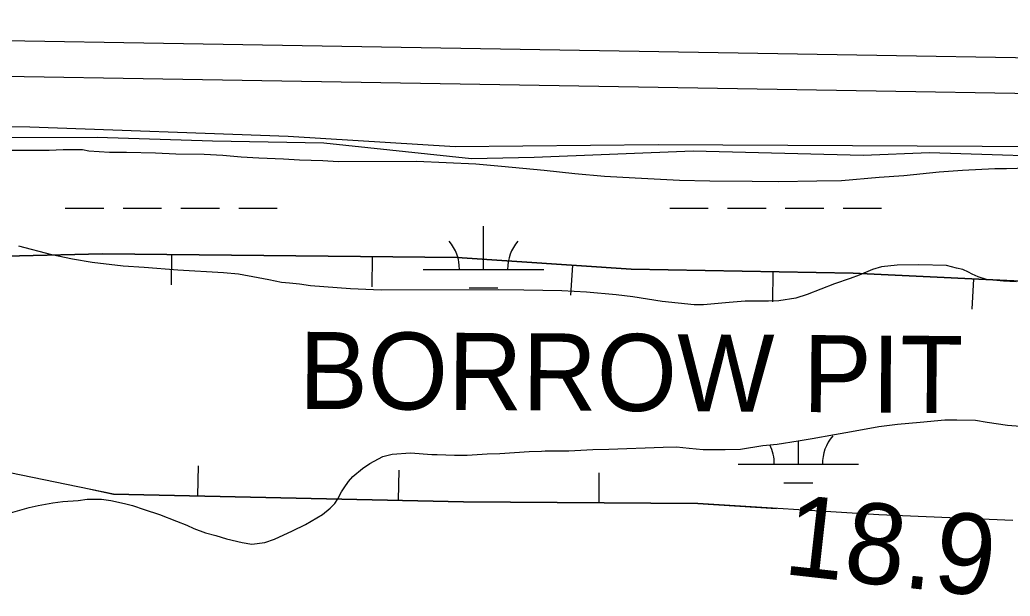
# Model space of a CAD drawing. Extents: x 3445503 to 3483459, y 540493 to 566012.
# Drawn here: x 3465896 to 3466718, y 552977 to 553456 of the extents above; entities that cross this region are included whole.
import ezdxf

# ---------------------------------------------------------------- set-up
doc = ezdxf.new("R2010")
doc.units = 0
for name, color, linetype in [('V-BORW-IDEN', 7, 'Continuous'), ('V-BORW-LINE', 7, 'Continuous'), ('V-LEVE-TOET', 7, 'Continuous'), ('V-RIVR-RANG', 7, 'Continuous'), ('V-SITE-VEGE', 7, 'Continuous'), ('V-SURV-LINE', 7, 'Continuous'), ('V-WETL-SWMP', 7, 'Continuous')]:
    doc.layers.add(name, color=color, linetype=linetype)

msp = doc.modelspace()

# ---------------------------------------------------------------- linework, layer by layer
at = {"layer": 'V-BORW-LINE'}
for p, q in [((3466021.74, 553261.05), (3466021.49, 553236.05)), ((3466188.33, 553259.35), (3466188.08, 553234.35)), ((3466354.72, 553252.24), (3466353.05, 553227.3)), ((3466521.19, 553246.8), (3466520.73, 553221.81)), ((3466687.67, 553240.87), (3466686.49, 553215.9)), ((3466043.69, 553060.73), (3466044.24, 553085.72)), ((3466210.25, 553057.07), (3466210.8, 553082.07)), ((3466376.83, 553054.95), (3466377.04, 553079.94))]:
    msp.add_line(p, q, dxfattribs=at)
for points in [[(3464755.94, 553241.74), (3464860.3, 553253.78), (3464945.02, 553233.84), (3464976, 553179.35), (3465019.34, 553224.51), (3465044.07, 553250.35), (3465137.34, 553252.47), (3465300.09, 553251.41), (3465457.21, 553261.25), (3465601.57, 553261.39), (3465688.95, 553257.71), (3465814.69, 553258.09), (3465964.49, 553261.63), (3466258.98, 553258.64), (3466403.46, 553248.99), (3466587.71, 553245.57), (3466756.03, 553237.65)], [(3466756.03, 553237.65), (3466587.71, 553245.57), (3466403.46, 553248.99), (3466258.98, 553258.64), (3465964.49, 553261.63), (3465814.69, 553258.09), (3465688.95, 553257.71), (3465601.57, 553261.39), (3465457.21, 553261.25), (3465300.09, 553251.41), (3465137.34, 553252.47), (3465044.07, 553250.35), (3465019.34, 553224.51), (3464976, 553179.35), (3464945.02, 553233.84), (3464860.3, 553253.78), (3464755.94, 553241.74)], [(3466720.32, 553040.35), (3466609.07, 553044.93), (3466458.87, 553054.26), (3466264.38, 553055.88), (3465973.67, 553062.27), (3465790.42, 553099.82), (3465601.82, 553107.72), (3465427.44, 553085.02), (3465258.2, 553090.06), (3465125.53, 553090.31), (3464961.14, 553070.6), (3464793.44, 553028.89)], [(3465954.38, 553066.22), (3465973.67, 553062.27), (3466264.38, 553055.88), (3466458.87, 553054.26), (3466524.1, 553050.21)]]:
    msp.add_lwpolyline(points, dxfattribs=at)
at = {"layer": 'V-LEVE-TOET'}
msp.add_lwpolyline([(3465299.58, 553374.06), (3465570.24, 553371.6), (3465904.01, 553367.37), (3466118.73, 553359.54), (3466257.34, 553350.84), (3466425.84, 553352.63), (3466748.55, 553350.98), (3467041.34, 553344.68), (3467298.34, 553340.88)], dxfattribs=at)
at = {"layer": 'V-SITE-VEGE'}
for points in [[(3465881.66, 553347.86), (3465920.18, 553347.98), (3465931.86, 553348.33), (3465947.96, 553348.37), (3465953.02, 553347.44), (3465970.38, 553346.23), (3465984.27, 553346.27), (3466008.59, 553345.71), (3466025.32, 553344.81), (3466049, 553344.56), (3466064.48, 553343.66), (3466079.64, 553342.45), (3466094.16, 553341.54), (3466114.68, 553340.65), (3466127.95, 553339.74), (3466147.53, 553339.17), (3466160.16, 553338.58), (3466225.2, 553338.77), (3466274.46, 553336.39), (3466295.93, 553334.56), (3466331.3, 553331.18), (3466356.57, 553328.42), (3466381.2, 553326.28), (3466406.78, 553324.77), (3466443.72, 553322.99), (3466468.67, 553322.43), (3466504.03, 553322.22), (3466525.82, 553321.97), (3466557.71, 553322.38), (3466578.23, 553322.75), (3466609.48, 553325.37), (3466629.99, 553326.69), (3466659.35, 553329.94), (3466678.6, 553331.25), (3466705.44, 553332.6), (3466715.22, 553332.62), (3466742.06, 553333.33)], [(3466723.2, 553238.55), (3466712.78, 553239.15), (3466698.56, 553240.37), (3466691.61, 553242.56), (3466686.55, 553244.76), (3466683.71, 553246.64), (3466678.96, 553248.84), (3466673.6, 553249.77), (3466665.38, 553251.96), (3466642.33, 553252.52), (3466624.33, 553252.47), (3466611.39, 553250.85), (3466603.82, 553248.62), (3466592.79, 553244.17), (3466585.22, 553241.3), (3466572.29, 553236.84), (3466549.58, 553227.94), (3466540.12, 553225.07), (3466526.23, 553222.82), (3466517.39, 553222.48), (3466498.13, 553222.42), (3466484.87, 553221.43), (3466463.41, 553219.48), (3466455.83, 553219.45), (3466429.3, 553222.22), (3466404.98, 553225.94), (3466391.08, 553227.79), (3466366.45, 553229.93), (3466345.93, 553231.13), (3466314.35, 553231.67), (3466293.2, 553231.92), (3466195.95, 553231.64), (3466170.38, 553232.82), (3466137.22, 553235.25), (3466128.06, 553236.49), (3466119.84, 553237.41), (3466113.21, 553238.02), (3466102.47, 553240.2), (3466093.63, 553241.76), (3466077.52, 553244.87), (3466064.89, 553246.09), (3466026.99, 553248.19), (3465999.2, 553250.32), (3465981.52, 553251.53), (3465955.93, 553254.61), (3465939.51, 553257.41), (3465922.45, 553260.83), (3465894.96, 553268.01)], [(3466122.34, 553031.57), (3466133.06, 553036.96), (3466147.25, 553045.21), (3466153.54, 553050.6), (3466157.32, 553054.4), (3466159.84, 553058.2), (3466162.98, 553064.2), (3466165.18, 553067.37), (3466168.64, 553072.74), (3466172.41, 553076.86), (3466180.29, 553083.52), (3466186.59, 553087.64), (3466197.31, 553093.35), (3466204.88, 553095.27), (3466220.35, 553096.58), (3466238.03, 553095.05), (3466242.45, 553095.06), (3466256.66, 553094.47), (3466267.39, 553094.51), (3466283.81, 553095.5), (3466294.54, 553095.85), (3466318.85, 553097.5), (3466328.95, 553097.84), (3466332.11, 553098.17), (3466351.68, 553098.22), (3466371.57, 553099.23), (3466384.83, 553099.58), (3466429.97, 553101.3), (3466441.02, 553101.33), (3466451.76, 553100.41), (3466463.13, 553099.18), (3466481.44, 553099.24), (3466494.39, 553099.59), (3466512.69, 553102.49), (3466524.68, 553103.79), (3466542.04, 553106.36), (3466553.72, 553108.29), (3466572.34, 553111.82), (3466586.54, 553114.07), (3466609.26, 553118.24), (3466624.72, 553120.18), (3466643.35, 553121.81), (3466663.86, 553123.77), (3466673.96, 553123.8), (3466689.44, 553123.53), (3466699.23, 553121.97), (3466715.97, 553119.5), (3466726.71, 553118.58)], [(3465886.14, 553046.03), (3465903.49, 553051.13), (3465911.06, 553052.73), (3465923.37, 553054.98), (3465931.57, 553055.95), (3465944.2, 553056.93), (3465951.77, 553057.9), (3465963.77, 553057.94), (3465971.35, 553057.01), (3465982.73, 553054.52), (3465989.36, 553052.65), (3465999.16, 553049.52), (3466011.8, 553045.13), (3466026.02, 553039.81), (3466034.56, 553036.36), (3466040.25, 553033.53), (3466050.04, 553030.09), (3466058.58, 553027.91), (3466067.43, 553025.09), (3466080.38, 553021.97), (3466088.6, 553020.73), (3466099.32, 553022.03), (3466107.21, 553024.89), (3466122.34, 553031.57)]]:
    msp.add_lwpolyline(points, dxfattribs=at)
at = {"layer": 'V-SURV-LINE'}
for points in [[(3464863.25, 553456.14), (3468482.67, 553395.22)], [(3468482.16, 553365.23), (3464862.74, 553426.15)]]:
    msp.add_lwpolyline(points, dxfattribs=at)
at = {"layer": 'V-WETL-SWMP'}
for p, q in [((3465933.55, 553299.55), (3465965.55, 553299.55)), ((3465981.55, 553299.55), (3466013.55, 553299.55)), ((3466029.55, 553299.55), (3466061.55, 553299.55)), ((3466077.55, 553299.55), (3466109.55, 553299.55)), ((3466435.46, 553299.55), (3466467.46, 553299.55)), ((3466483.46, 553299.55), (3466515.46, 553299.55)), ((3466531.46, 553299.55), (3466563.46, 553299.55)), ((3466579.46, 553299.55), (3466611.46, 553299.55)), ((3466280.87, 553248.81), (3466280.87, 553284.81)), ((3466230.87, 553248.81), (3466330.87, 553248.81)), ((3466268.87, 553233.38), (3466292.87, 553233.38)), ((3466542.3, 553086.96), (3466542.3, 553106.42)), ((3466492.3, 553086.96), (3466592.3, 553086.96)), ((3466530.3, 553071.53), (3466554.3, 553071.53))]:
    msp.add_line(p, q, dxfattribs=at)
for points in [[(3465668.38, 553359.01), (3465710.74, 553356.2), (3465786.65, 553358.38), (3465959.98, 553358.56), (3466055.78, 553355.59), (3466148.32, 553353.9), (3466270.86, 553340.9), (3466322.99, 553342.03), (3466454.93, 553347.31), (3466596.02, 553343.81), (3466651.08, 553345.93), (3466789.89, 553341.45)], [(3465922.45, 553260.83), (3465894.96, 553268.01)], [(3466723.2, 553238.55), (3466712.78, 553239.15), (3466698.56, 553240.37), (3466691.61, 553242.56), (3466686.56, 553244.76), (3466683.71, 553246.64), (3466678.96, 553248.84), (3466673.6, 553249.77), (3466665.38, 553251.96), (3466642.33, 553252.52), (3466624.33, 553252.47), (3466611.39, 553250.85), (3466603.82, 553248.62), (3466592.79, 553244.17), (3466585.22, 553241.3), (3466572.29, 553236.84), (3466549.58, 553227.94), (3466540.12, 553225.07), (3466526.23, 553222.82), (3466517.39, 553222.48), (3466498.13, 553222.42), (3466484.87, 553221.43), (3466463.41, 553219.48), (3466455.83, 553219.45), (3466429.3, 553222.22), (3466404.98, 553225.94), (3466391.08, 553227.79), (3466366.45, 553229.93), (3466345.93, 553231.13), (3466314.35, 553231.67), (3466293.2, 553231.92), (3466195.95, 553231.64), (3466170.38, 553232.82), (3466137.22, 553235.25), (3466128.06, 553236.49), (3466119.85, 553237.41), (3466113.21, 553238.03), (3466102.47, 553240.2), (3466093.63, 553241.76), (3466077.52, 553244.87), (3466064.88, 553246.09), (3466026.99, 553248.19), (3465999.2, 553250.32), (3465981.52, 553251.53), (3465955.93, 553254.61), (3465939.51, 553257.41), (3465922.45, 553260.83)], [(3465999.16, 553049.52), (3466011.8, 553045.13), (3466026.02, 553039.81), (3466034.56, 553036.36), (3466040.25, 553033.54), (3466050.05, 553030.09), (3466058.58, 553027.91), (3466067.43, 553025.09), (3466080.38, 553021.97), (3466088.59, 553020.73), (3466099.32, 553022.03), (3466107.21, 553024.89), (3466122.34, 553031.57), (3466133.06, 553036.96), (3466147.25, 553045.21), (3466153.54, 553050.6), (3466157.32, 553054.4), (3466159.84, 553058.2), (3466162.98, 553064.2), (3466165.18, 553067.37), (3466168.64, 553072.75), (3466172.41, 553076.86), (3466180.29, 553083.52), (3466186.59, 553087.64), (3466197.31, 553093.35), (3466204.88, 553095.27), (3466220.34, 553096.58), (3466238.03, 553095.05), (3466242.45, 553095.06), (3466256.66, 553094.47), (3466267.39, 553094.51), (3466283.81, 553095.5), (3466294.54, 553095.85), (3466318.85, 553097.5), (3466328.95, 553097.84), (3466332.11, 553098.17), (3466351.68, 553098.22), (3466371.57, 553099.23), (3466384.83, 553099.58), (3466429.97, 553101.3), (3466441.02, 553101.33), (3466451.76, 553100.41), (3466463.13, 553099.18), (3466481.44, 553099.24), (3466494.39, 553099.59), (3466512.69, 553102.49), (3466524.68, 553103.78), (3466542.04, 553106.36), (3466553.72, 553108.29), (3466572.34, 553111.82), (3466586.54, 553114.07), (3466609.26, 553118.24), (3466624.72, 553120.18), (3466643.35, 553121.81), (3466663.86, 553123.77), (3466673.96, 553123.8), (3466689.44, 553123.53), (3466699.23, 553121.98), (3466715.97, 553119.5), (3466726.71, 553118.58)], [(3465886.14, 553046.03), (3465903.49, 553051.13), (3465911.06, 553052.73), (3465923.37, 553054.98), (3465931.57, 553055.95), (3465944.2, 553056.93), (3465951.77, 553057.9), (3465963.77, 553057.94), (3465971.35, 553057.01), (3465982.73, 553054.52), (3465989.36, 553052.65), (3465999.16, 553049.52)]]:
    msp.add_lwpolyline(points, dxfattribs=at)
for centre, start, end in [((3466225.62, 553249.29), 359.22821, 40.77186), ((3466336.11, 553249.29), 139.22815, 180.77181), ((3466597.54, 553087.43), 139.22815, 180.77181), ((3466487.06, 553087.43), 359.22821, 26.48215)]:
    msp.add_arc(centre, 35.25, start, end, dxfattribs=at)

# ---------------------------------------------------------------- texts
at = {"layer": 'V-BORW-IDEN'}
msp.add_text('BORROW PIT', height=64, rotation=359.62952, dxfattribs=at).set_placement((3466127.5, 553133.03))
at = {"layer": 'V-RIVR-RANG'}
msp.add_text('18.9', height=67, rotation=353.62833, dxfattribs=at).set_placement((3466528.86, 552995.93))

doc.saveas('drawing.dxf')
